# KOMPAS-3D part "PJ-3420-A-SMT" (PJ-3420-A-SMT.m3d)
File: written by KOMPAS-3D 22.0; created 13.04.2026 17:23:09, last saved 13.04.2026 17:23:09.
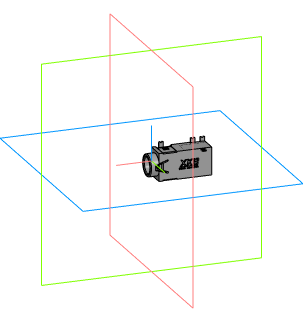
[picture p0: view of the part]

Document properties: Автор: Andrey; Полное имя файла: C:\Users\User1\Documents\PJ-3420-A-SMT.m3d

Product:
- Part/product: PJ-3420-A-SMT
    Комментарий: NOT SPECIFIED

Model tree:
1. Операция без истории:1
2. Операция без истории:2
3. Операция без истории:3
